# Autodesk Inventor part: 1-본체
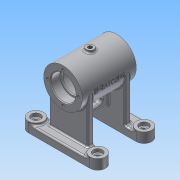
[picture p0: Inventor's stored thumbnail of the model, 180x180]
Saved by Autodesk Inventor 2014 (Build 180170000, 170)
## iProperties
Created: 2015-11
Part Number: 1-본체
Material: 알루미늄 6061
Document SubType Name: Modeling
Designer: 103-30
Mass: 358.954 g
Surface Area: 460.522 cm^2
Volume: 132.455 cm^3
Density: 2.71 g/cm^3
Appearance: 알루미늄 - 평지
Author: 103-30
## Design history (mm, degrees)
sketch "스케치1"
  geometry: L1 (-40, 40)-(40, 40); L2 (40, 20)-(-40, 20); L3 (-40, -20)-(40, -20); L4 (40, -40)-(-40, -40); A1 r 10 centre (40, 30) between (40, 20) and (40, 40); A2 r 10 centre (-40, 30) between (-40, 40) and (-40, 20); A3 r 10 centre (40, -30) between (40, -40) and (40, -20); A4 r 10 centre (-40, -30) between (-40, -20) and (-40, -40); 3 further points
  constraints: 8 end point, 8 point on circle, 8 tangent, 4 centre point, 3 parallel, 2 midpoint, 2 vertical alignment, 1 horizontal
  dimensions: "d0" = 20 distance between parallel lines of L2 L1; "d1" = 40 distance from line of L1 point (0, 0); "d2" = 80 distance of A1.centre A2.centre; "d3" = 80 distance of A3.centre A4.centre; "d4" = 20 distance between parallel lines of L4 L3; "d5" = 40 distance from line of point (0, 0) L4
extrude "돌출1" new body sketch "스케치1" distance "d6" = 10; taper "d7" = 0 deg
sketch "스케치2"
  geometry: L1 (40, 40)-(-40, 40) reference; L2 (-40, 20)-(40, 20) reference; C1 r 10 at (-40, 30); C2 r 10 at (40, 30); C3 r 10 at (40, -30); C4 r 10 at (-40, -30); A1 r 10 centre (-40, -30) between (-40, -20) and (-40, -40) reference; A2 r 10 centre (40, -30) between (40, -40) and (40, -20) reference; A3 r 10 centre (-40, 30) between (-40, 40) and (-40, 20) reference; A4 r 10 centre (40, 30) between (40, 20) and (40, 40) reference; 1 further point
  constraints: 4 centre point, 4 coincident
  dimensions: "d8" = 20 diameter of C1; "d9" = 20 diameter of C2; "d10" = 20 diameter of C3; "d11" = 20 diameter of C4
extrude "돌출2" join sketch "스케치2" distance "d12" = 3; taper "d13" = 0 deg
node "작업 평면1"
sketch "스케치3"
  geometry: L1 (-35, 68)-(35, 68); L2 (20, 0)-(40, 0) reference; L3 (-35, 84)-(-23, 84); L4 (-23, 84)-(-23, 82); L5 (-23, 82)-(-21, 82); L6 (-21, 82)-(-21, 89); L7 (-21, 89)-(21, 89); L8 (21, 89)-(21, 82); L9 (21, 82)-(23, 82); L10 (23, 82)-(23, 84); L11 (23, 84)-(35, 84); L12 (35, 84)-(35, 93); L13 (35, 93)-(-35, 93); L14 (-35, 93)-(-35, 84); 1 further point
  constraints: 26 end point, 10 parallel, 1 collinear, 1 horizontal, 1 perpendicular, 1 point on line
  dimensions: "d15" = 70 distance of L1.start L1.end; "d16" = 68 distance between parallel lines of L2 L1; "d17" = 35 horizontal distance of L1.start point (0, 0); "d18" = 28 diameter of L5 L1; "d19" = 28 diameter of L9 L1; "d20" = 32 diameter of L11 L1; "d21" = 32 diameter of L3 L1; "d22" = 50 diameter of L13 L1; "d23" = 42 diameter of L7 L1; "d24" = 12 distance of L3.start L3.end; "d25" = 2 distance of L4.end L5.end; "d26" = 42 distance of L6.end L7.end; "d27" = 2 distance of L8.end L9.end; "d28" = 12 distance of L10.end L11.end
revolve "회전1" sketch "스케치3" stored, may be unused: angle "d29" = 90 deg
sketch "스케치4"
  geometry: L1 (80, -10)-(0, -10) reference; L2 (80, 0)-(80, -10) reference; L3 (65, -10)-(65, -68); L4 (15, -10)-(15, -68); L5 (65, -68)-(62.138, -68); L6 (15, -68)-(17.551, -68); L7 (65, -10)-(15, -10); C1 r 14 at (40, -68) reference; C2 r 21 at (40, -68) reference; A1 r 25 centre (40, -68) between (65, -68) and (15, -68) reference; A2 r 22.449 centre (40, -68) between (62.449, -68) and (17.551, -68); 1 further point
  constraints: 10 end point, 4 point on circle, 3 parallel, 3 point on line, 2 tangent, 1 centre point, 1 collinear, 1 perpendicular
  dimensions: "d32" = 44.89837 diameter of A2
extrude "돌출3" join sketch "스케치4" distance "d33" = 8; taper "d34" = 0 deg
node "작업 평면2"
sketch "스케치5"
  geometry: L1 (-35, 43)-(35, 43) reference; L2 (-35, 52)-(-35, 84) reference; L3 (-28, 68)-(-28, 10) reference; L4 (-20, 10)-(-20, 68) reference; L5 (28, 68)-(28, 10) reference; L6 (20, 10)-(20, 68) reference; L7 (20, 10)-(28, 10) reference; L8 (-28, 10)-(-20, 10) reference; L9 (-28, 23)-(28, 23); L10 (-28, 43)-(-28, 23); L11 (-28, 43)-(28, 43); L12 (28, 23)-(28, 43); L13 (-8, 36.5)-(8, 36.5); L14 (8, 29.5)-(-8, 29.5); L15 (20, 0)-(40, 0) reference; L16 (-28, 43)-(-28, 45.207); L17 (-28, 45.207)-(28, 45.207); L18 (28, 45.207)-(28, 43); A1 r 3.5 centre (8, 33) between (8, 29.5) and (8, 36.5); A2 r 3.5 centre (-8, 33) between (-8, 36.5) and (-8, 29.5); 2 further points
  constraints: 18 end point, 6 point on line, 4 point on circle, 4 tangent, 3 perpendicular, 2 centre point, 2 collinear, 2 parallel, 1 midpoint, 1 vertical alignment
  dimensions: "d36" = 20 distance between parallel lines of L9 L1; "d37" = 23 dimension on A1 A2; "d38" = 33 distance from line of A1.centre L15; "d39" = 3.5 radius of A1; "d40" = 22.20704 distance between parallel lines of L9 L17
extrude "돌출4" join sketch "스케치5" stored distance "d41" = 8; taper "d42" = 0 deg
extrude "돌출5" cut sketch "스케치5" stored distance "d43" = 8; taper "d44" = 0 deg
node "작업 평면3"
sketch "스케치6"
  geometry: C1 r 5 at (0, 0); 1 further point
  constraints: 1 centre point, 1 coincident
  dimensions: "d46" = 10 diameter of C1
extrude "돌출6" join sketch "스케치6" stored distance "d47" = 8; taper "d48" = 0 deg
node "작업 평면6"
  node "작업 평면5"
sketch "스케치7"
  geometry: L1 (35, 25)-(35, -25) reference; L2 (-35, 25)-(-35, -25) reference; L3 (35, 25)-(-35, 25) reference; L4 (-35, 25)-(-35, -25) reference; L5 (35, 25)-(35, -25) reference; L6 (20, -15.803)-(-20, -15.803) reference; L7 (-20, -15.803)-(-20, -21.651) reference; L8 (-20, -21.651)-(-28, -21.651) reference; L9 (-28, -21.651)-(-28, 21.651) reference; L10 (-20, 21.651)-(-28, 21.651) reference; L11 (-20, 21.651)-(-20, -8.875) reference; L12 (-20, -8.875)-(20, -8.875) reference; L13 (20, -8.875)-(20, 21.651) reference; L14 (28, 21.651)-(20, 21.651) reference; L15 (28, 21.651)-(28, -21.651) reference; L16 (28, -21.651)-(20, -21.651) reference; L17 (20, -21.651)-(20, -15.803) reference; L18 (35, 25)-(-35, 25) reference; L19 (-23, 14)-(-23, -14) reference; L20 (-35, 16)-(-35, -16) reference; C1 r 6 at (0, 0); 6 further points
  constraints: 2 midpoint, 1 centre point, 1 horizontal alignment, 1 vertical alignment, 2 other
  dimensions: "d51" = 12 diameter of C1
extrude "돌출7" join sketch "스케치7" stored distance "d52" = 8; taper "d53" = 0 deg
hole "구멍1" diameter "d56" = 6; stored, may be unused: countersink angle "d60" = 90 deg, drill point angle "d62" = 118 deg; dims "d54" = 10, "d55" = 10, "d57" = 6, "d58" = 12, "d59" = 4, "d61" = 8
sketch "스케치8"
  geometry: C1 r 10 at (0, 0) reference; C2 r 10 at (80, 0) reference; C3 r 10 at (80, -60) reference; 4 further points
  constraints: 3 coincident
hole "구멍2" sketch "스케치8" at (0, 0), (80, 0), (80, -60) diameter "d63" = 6; stored, may be unused: countersink angle "d67" = 90 deg, drill point angle "d69" = 118 deg; dims "d64" = 6, "d65" = 12, "d66" = 4, "d68" = 8
sketch "스케치9"
  geometry: C1 r 16 at (0, 0) reference; C2 r 25 at (0, 0) reference; A1 r 20 centre (0, 0) between (0, 20) and (-20, 0); 3 further points
  constraints: 4 point on circle, 2 horizontal alignment, 2 vertical alignment, 1 centre point, 1 coincident
  dimensions: "d70" = 40 diameter of A1
hole "구멍3" sketch "스케치9" at (0, 20), (-20, 0), (20, 0), (0, -20) diameter "d71" = 3.242; stored, may be unused: countersink angle "d75" = 90 deg, drill point angle "d77" = 118 deg; dims "d72" = 8, "d73" = 12, "d74" = 4, "d76" = 10
hole "구멍4" diameter "d80" = 5.188; stored, may be unused: countersink angle "d84" = 90 deg, drill point angle "d86" = 0 deg; dims "d78" = 10, "d79" = 10, "d81" = 8, "d82" = 12, "d83" = 4, "d85" = 10
hole "구멍5" diameter "d89" = 5.188; stored, may be unused: countersink angle "d93" = 90 deg, drill point angle "d95" = 0 deg; dims "d87" = 10, "d88" = 10, "d90" = 8, "d91" = 12, "d92" = 4, "d94" = 10
node "작업 평면7"
sketch "스케치10"
  geometry: L1 (-35, -25)-(-35, 25) reference; L2 (-35, 25)-(35, 25) reference; 2 further points
  constraints: 1 other
  dimensions: "d96" = 35 distance from line of L1 point (0, 0); "d97" = 25 distance from line of L2 point (0, 0)
feature "엠보싱1" sketch "스케치10" dims "d0" = 20, "d1" = 40, "d2" = 80, "d3" = 80, "d4" = 20, "d5" = 40, "d98" = 0.5, "d99" = 0
fillet "모깎기1" dims "d100" = 0.3
fillet "모깎기2" dims "d101" = 3
fillet "모깎기3" dims "d102" = 2
fillet "모깎기4" dims "d103" = 2
fillet "모깎기5" dims "d104" = 2
fillet "모깎기6" dims "d105" = 2
fillet "모깎기7" dims "d106" = 2
chamfer "모따기1" distance "d107" = 1; stored, may be unused: second distance "d108" = 2, angle "d109" = 45 deg
fillet "모깎기8" dims "d110" = 2
fillet "모깎기9" dims "d111" = 2
fillet "모깎기10" dims "d112" = 2
fillet "모깎기11" dims "d113" = 2
node "솔리드1"
mirror "대칭1"
mirror "대칭2"
node "투영된 루프1"
node "작업 평면4"
node "투영된 루프2"
node "투영된 루프3"
node "투영된 루프4"
other parameters: "d14" = 0, "d35" = 0, "d45" = 96, "d49" = 30 deg, "d50" = -3
